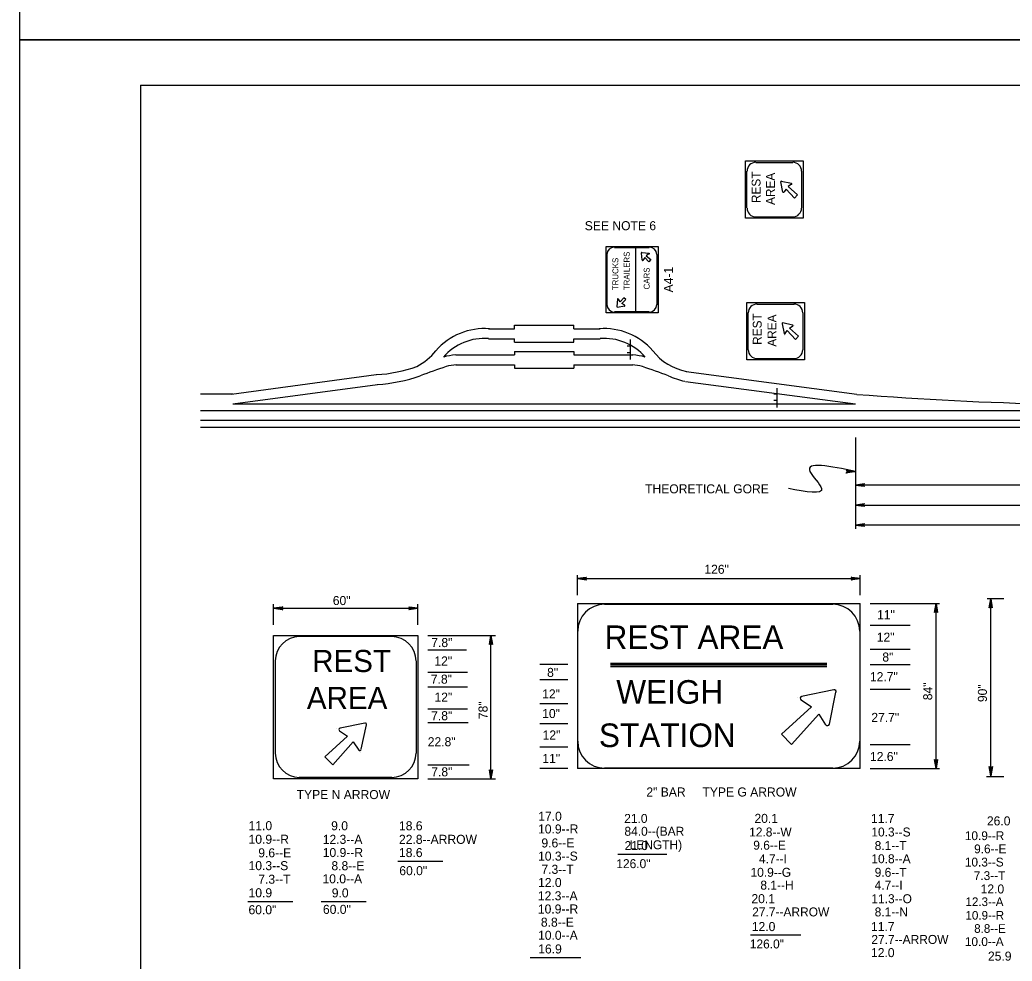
# Model space of a CAD drawing. Extents: x 649604 to 650509, y 298458 to 299646.
# Drawn here: x 649604.3 to 649933.2, y 298746.1 to 299058.3 of the extents above; entities that cross this region are included whole.
import ezdxf

# ---------------------------------------------------------------- set-up
doc = ezdxf.new("R2010")
doc.units = 0
for name, color, linetype in [('1', 7, 'Continuous'), ('2', 7, 'Continuous'), ('3', 7, 'Continuous'), ('PLT-BNDY', 7, 'Continuous')]:
    doc.layers.add(name, color=color, linetype=linetype)

# ---------------------------------------------------------------- blocks, each defined once
blk = doc.blocks.new('RARROW')
at = {"layer": '3'}
blk.add_lwpolyline([(-2.2695, 0.285), (-2.184875, 0.12075), (0, 0), (-2.2695, 0.285), (-2.38575, 0.384625), (0, 0), (-2.183125, -0.108), (-2.262875, -0.2705), (0, 0), (-2.38575, -0.379125), (-2.262875, -0.2705)], dxfattribs=at)

msp = doc.modelspace()

# ---------------------------------------------------------------- linework, layer by layer
at = {"layer": '1'}
for q in [(650430.31, 299036.63), (649644.31, 298472.63)]:
    msp.add_line((649644.31, 299036.63), q, dxfattribs=at)
at = {"layer": '2'}
for p, q in [((649848.31, 299011), (649860.56, 299011)), ((649856.56, 299004.75), (649856.56, 299004.75)), ((649857.19, 299001.13), (649856.56, 299004.5)), ((649856.69, 299004.75), (649860.06, 299004.13)), ((649860.06, 299003.75), (649858.94, 299003)), ((649858.31, 299002.13), (649857.56, 299001.13)), ((649861.06, 298999.13), (649858.31, 299002.13)), ((649858.31, 299002.13), (649858.31, 299002.13)), ((649858.94, 299003), (649858.94, 299003)), ((649858.94, 299003), (649862.06, 299000.25)), ((649862.06, 299000.25), (649861.06, 298999.13)), ((649863.94, 298992.5), (649844.81, 298992.5)), ((649860.56, 298992.88), (649848.31, 298992.88)), ((649801.44, 298982.75), (649812.94, 298982.75)), ((649808.44, 298961.5), (649808.44, 298982.75)), ((649810.56, 298978.63), (649810.31, 298980.88)), ((649810.56, 298981.13), (649812.81, 298980.88)), ((649810.56, 298981), (649810.56, 298981)), ((649812.81, 298980.63), (649811.94, 298980)), ((649812.81, 298980.63), (649812.81, 298980.63)), ((649812.94, 298980.63), (649812.94, 298980.63)), ((649812.94, 298980.63), (649812.94, 298980.63)), ((649810.69, 298978.63), (649810.69, 298978.63)), ((649810.69, 298978.38), (649810.69, 298978.38)), ((649810.69, 298978.38), (649810.69, 298978.38)), ((649811.44, 298979.5), (649810.81, 298978.5)), ((649812.81, 298978), (649811.44, 298979.5)), ((649811.44, 298979.5), (649811.44, 298979.5)), ((649811.69, 298979.75), (649811.69, 298979.75)), ((649811.94, 298980), (649811.94, 298980)), ((649811.94, 298980), (649813.44, 298978.75)), ((649813.44, 298978.75), (649812.81, 298978)), ((649812.81, 298978), (649812.81, 298978)), ((649813.44, 298978.75), (649813.44, 298978.75)), ((649802.44, 298965.63), (649802.19, 298963.25)), ((649802.56, 298965.88), (649802.56, 298965.88)), ((649803.31, 298964.75), (649802.69, 298965.63)), ((649804.56, 298966.13), (649803.31, 298964.75)), ((649803.81, 298964.25), (649805.19, 298965.5)), ((649803.81, 298964.25), (649803.81, 298964.25)), ((649804.81, 298963.63), (649803.81, 298964.25)), ((649805.19, 298965.5), (649804.56, 298966.13)), ((649800.94, 298961.13), (649799.31, 298961.13)), ((649801.44, 298961.5), (649812.94, 298961.5)), ((649802.19, 298963.13), (649802.19, 298963.13)), ((649802.31, 298963), (649804.81, 298963.38)), ((649804.81, 298963.5), (649804.81, 298963.5)), ((649804.81, 298963.5), (649804.81, 298963.5)), ((649808.81, 298961.13), (649807.81, 298961.13)), ((649848.69, 298964), (649860.94, 298964)), ((649856.81, 298957.75), (649856.81, 298957.75)), ((649860.44, 298957), (649857.19, 298957.75)), ((649759.69, 298955.75), (649768.31, 298955.75)), ((649768.31, 298957), (649787.94, 298957)), ((649768.31, 298955.75), (649768.31, 298957)), ((649787.94, 298955.75), (649787.94, 298957)), ((649787.94, 298955.75), (649796.69, 298955.75)), ((649856.94, 298957.5), (649857.69, 298954.25)), ((649857.94, 298954.25), (649858.69, 298955.25)), ((649858.69, 298955.25), (649858.69, 298955.25)), ((649858.69, 298955.25), (649861.44, 298952.25)), ((649859.44, 298956), (649860.56, 298956.75)), ((649862.44, 298953.38), (649859.44, 298956)), ((649859.44, 298956), (649859.44, 298956)), ((649860.94, 298957), (649860.94, 298957)), ((649759.69, 298952.5), (649768.31, 298952.5)), ((649768.31, 298951.38), (649768.31, 298952.5)), ((649768.31, 298951.38), (649787.94, 298951.38)), ((649787.94, 298951.38), (649787.94, 298952.5)), ((649787.94, 298952.5), (649796.69, 298952.5)), ((649806.69, 298945.63), (649806.69, 298952.25)), ((649857.81, 298953.75), (649857.81, 298953.75)), ((649861.44, 298952.25), (649862.44, 298953.38)), ((649768.31, 298948.25), (649787.94, 298948.25)), ((649768.31, 298948.25), (649768.31, 298947.13)), ((649787.94, 298948.25), (649787.94, 298947.13)), ((649806.69, 298950), (649805.56, 298950)), ((649806.69, 298947.88), (649805.56, 298947.88)), ((649748.81, 298947.13), (649768.31, 298947.13)), ((649787.94, 298947.13), (649807.44, 298947.13)), ((649864.44, 298945.5), (649845.31, 298945.5)), ((649860.94, 298945.88), (649848.69, 298945.88)), ((649748.81, 298943.88), (649768.31, 298943.88)), ((649768.31, 298943.88), (649768.31, 298942.75)), ((649768.31, 298942.75), (649787.94, 298942.75)), ((649787.94, 298943.88), (649787.94, 298942.75)), ((649787.94, 298943.88), (649807.44, 298943.88)), ((649825.19, 298941.63), (649881.69, 298934.13)), ((649674.44, 298934.13), (649722.44, 298940.63)), ((649824.94, 298938.38), (649824.94, 298938.38)), ((649824.94, 298938.38), (649881.31, 298930.88)), ((649674.94, 298930.88), (649722.81, 298937.38)), ((649722.81, 298937.38), (649722.81, 298937.38)), ((649722.81, 298937.38), (649722.81, 298937.38)), ((649855.31, 298929.75), (649855.31, 298936.13)), ((649674.94, 298934.13), (649664.19, 298934.13)), ((649855.31, 298934.13), (649854.19, 298934.13)), ((649855.31, 298932), (649854.19, 298932)), ((649664.19, 298928.75), (650390.69, 298928.75)), ((649674.94, 298930.88), (649881.31, 298930.88)), ((649674.94, 298930.88), (649674.94, 298930.88)), ((649674.94, 298930.88), (649674.94, 298930.88)), ((649664.19, 298925.5), (650390.69, 298925.5)), ((649664.19, 298923.25), (650390.69, 298923.25)), ((649881.31, 298919.75), (649881.31, 298889.5)), ((650085.69, 298904), (649881.31, 298904)), ((649881.31, 298897.38), (650176.94, 298897.38)), ((650311.69, 298890.75), (649881.31, 298890.75)), ((649789.13, 298867.47), (649789.13, 298874.13)), ((649789.13, 298873), (649882.88, 298873)), ((649882.88, 298867.47), (649882.88, 298874.13)), ((649930.47, 298866.25), (649924.9, 298866.25)), ((649926.15, 298807.63), (649926.15, 298866.25)), ((649688.44, 298857.65), (649688.44, 298864.5)), ((649688.44, 298863.13), (649736.19, 298863.13)), ((649736.19, 298857.65), (649736.19, 298864.5)), ((649789.13, 298864.75), (649882.88, 298864.75)), ((649789.13, 298864.75), (649789.13, 298810)), ((649798.15, 298864.49), (649873.75, 298864.49)), ((649882.88, 298810), (649882.88, 298864.75)), ((649886.17, 298864.75), (649909.12, 298864.75)), ((649908, 298810), (649908, 298864.75)), ((649886.17, 298857.5), (649899.45, 298857.5)), ((649688.44, 298806.63), (649688.44, 298854.13)), ((649739.56, 298854.13), (649761.94, 298854.13)), ((649760.44, 298806.63), (649760.44, 298854.13)), ((649789.21, 298819.06), (649789.21, 298855.55)), ((649882.7, 298855.55), (649882.7, 298819.06)), ((649739.56, 298849.38), (649752.33, 298849.38)), ((649886.17, 298849.63), (649899.45, 298849.63)), ((649688.94, 298845.63), (649688.94, 298815.13)), ((649735.81, 298815.13), (649735.81, 298845.63)), ((649785.9, 298844.5), (649776.63, 298844.5)), ((649800.13, 298845), (649871.76, 298845)), ((649800.13, 298844.88), (649871.76, 298844.88)), ((649800.13, 298844.5), (649871.76, 298844.5)), ((649800.13, 298844), (649871.76, 298844)), ((649800.13, 298843.88), (649871.76, 298843.88)), ((649886.17, 298844.5), (649899.45, 298844.5)), ((649739.56, 298842), (649752.68, 298842)), ((649785.9, 298839.38), (649776.63, 298839.38)), ((649739.56, 298837.13), (649752.68, 298837.13)), ((649874.13, 298836.13), (649863.38, 298833.88)), ((649874.13, 298836.13), (649863.38, 298833.88)), ((649875.01, 298836.38), (649875.01, 298836.38)), ((649886.17, 298836.38), (649899.45, 298836.38)), ((649862.01, 298833.63), (649862.01, 298833.63)), ((649863.26, 298832.75), (649866.76, 298830.5)), ((649863.26, 298832.75), (649866.76, 298830.5)), ((649872.63, 298824.75), (649874.76, 298835.38)), ((649872.63, 298824.75), (649874.76, 298835.38)), ((649739.56, 298829.75), (649752.68, 298829.75)), ((649785.9, 298831.5), (649776.63, 298831.5)), ((649866.76, 298830.5), (649856.76, 298821.38)), ((649866.76, 298830.5), (649856.76, 298821.38)), ((649866.76, 298830.5), (649866.76, 298830.5)), ((649867.88, 298829.25), (649867.88, 298829.25)), ((649860.13, 298818), (649869.13, 298828)), ((649860.13, 298818), (649869.13, 298828)), ((649869.13, 298828), (649871.38, 298824.5)), ((649869.13, 298828), (649869.13, 298828)), ((649869.13, 298828), (649871.38, 298824.5)), ((649709.31, 298823.13), (649709.31, 298823.13)), ((649718.69, 298825), (649710.44, 298823.38)), ((649717.44, 298816.38), (649719.19, 298824.5)), ((649719.31, 298825.25), (649719.31, 298825.25)), ((649739.56, 298825.25), (649752.91, 298825.25)), ((649785.9, 298824.88), (649776.63, 298824.88)), ((649872.38, 298823.25), (649872.38, 298823.25)), ((649712.94, 298820.75), (649705.44, 298813.88)), ((649710.31, 298822.5), (649712.94, 298820.75)), ((649712.94, 298820.75), (649712.94, 298820.75)), ((649856.76, 298821.38), (649860.13, 298818)), ((649856.76, 298821.38), (649856.76, 298821.38)), ((649856.76, 298821.38), (649860.13, 298818)), ((649708.06, 298811.25), (649714.81, 298818.88)), ((649714.81, 298818.88), (649714.81, 298818.88)), ((649714.81, 298818.88), (649716.69, 298816.13)), ((649785.9, 298817.13), (649776.63, 298817.13)), ((649860.13, 298818), (649860.13, 298818)), ((649886.17, 298818), (649899.45, 298818)), ((649705.44, 298813.88), (649708.06, 298811.25)), ((649717.19, 298815.25), (649717.19, 298815.25)), ((649739.56, 298811.25), (649753.26, 298811.25)), ((649785.9, 298810), (649776.63, 298810)), ((649882.88, 298810), (649789.13, 298810)), ((649873.75, 298810.12), (649798.15, 298810.12)), ((649886.17, 298810), (649909.12, 298810)), ((649739.56, 298806.63), (649761.94, 298806.63)), ((649930.47, 298807.27), (649924.77, 298807.27)), ((649802.47, 298781.61), (649818.72, 298781.61)), ((649729.65, 298779.34), (649744.51, 298779.34)), ((649679.92, 298765.97), (649694.77, 298765.97)), ((649704.19, 298765.97), (649719.1, 298765.97)), ((649846.53, 298754.86), (649863.15, 298754.86)), ((649773.49, 298747.38), (649790.28, 298747.38))]:
    msp.add_line(p, q, dxfattribs=at)
for points in [[(649844.81, 298992.5), (649844.81, 299011.5), (649846.81, 299011.5), (649849.81, 299011.5), (649851.69, 299011.5), (649854.56, 299011.5), (649856.56, 299011.5), (649862.19, 299011.5), (649863.94, 299011.5), (649863.94, 299011.5), (649863.94, 298992.5), (649863.94, 298992.5)], [(649845.31, 298995.88), (649845.31, 299008.13)], [(649863.44, 299008.13), (649863.44, 298995.88)], [(649798.69, 298961.13), (649798.69, 298983.13), (649800.31, 298983.13), (649802.19, 298983.13), (649803.69, 298983.13), (649805.69, 298983.13), (649807.06, 298983.13), (649808.56, 298983.13), (649811.81, 298983.13), (649815.94, 298983.13), (649815.94, 298961.13), (649811.19, 298961.13), (649809.31, 298961.13), (649807.06, 298961.13), (649804.69, 298961.13), (649801.44, 298961.13), (649798.69, 298961.13)], [(649798.94, 298963.75), (649798.94, 298980.5)], [(649815.44, 298980.5), (649815.44, 298963.75)], [(649845.31, 298945.5), (649845.31, 298964.5), (649847.31, 298964.5), (649850.19, 298964.5), (649852.06, 298964.5), (649855.06, 298964.5), (649856.81, 298964.5), (649862.56, 298964.5), (649864.44, 298964.5), (649864.44, 298964.5), (649864.44, 298945.5), (649864.44, 298945.5)], [(649845.69, 298948.88), (649845.69, 298961.13)], [(649863.81, 298961.13), (649863.81, 298948.88)], [(649688.44, 298854.13), (649736.19, 298854.13), (649736.19, 298849.38), (649736.19, 298842), (649736.19, 298837.13), (649736.19, 298829.75), (649736.19, 298825.25), (649736.19, 298811.25), (649736.19, 298806.63), (649736.19, 298806.63), (649688.44, 298806.63), (649688.44, 298806.63)], [(649727.56, 298853.75), (649696.94, 298853.75)], [(649696.94, 298807.13), (649727.56, 298807.13)]]:
    msp.add_lwpolyline(points, dxfattribs=at)
for centre, radius, start, end in [((649848.27, 299008.08), 2.93, 90, 180), ((649860.49, 299008.08), 2.93, 0, 90), ((649856.7, 299004.54), 0.183, 78.0958, 191.9043), ((649856.7, 299004.54), 0.183, 78.0958, 191.9043), ((649859.98, 299003.85), 0.183, 302.692, 78.0958), ((649859.98, 299003.85), 0.183, 302.692, 78.0958), ((649857.39, 299001.26), 0.183, 191.9043, 327.308), ((649857.39, 299001.26), 0.183, 191.9042, 327.308), ((649848.27, 298995.86), 2.93, 180, 270), ((649860.49, 298995.86), 2.93, 270, 0), ((649801.36, 298980.44), 2.44, 90, 180), ((649810.44, 298981), 0.153, 84.0498, 185.9502), ((649812.84, 298980.75), 0.153, 301.5539, 84.0498), ((649812.99, 298980.44), 2.44, 0, 90), ((649810.69, 298978.6), 0.153, 185.9502, 328.4461), ((649802.55, 298965.61), 0.153, 31.5539, 174.0498), ((649801.36, 298963.82), 2.44, 180, 270), ((649802.3, 298963.22), 0.153, 174.0498, 275.9502), ((649804.69, 298963.47), 0.153, 275.9502, 58.4461), ((649812.99, 298963.82), 2.44, 270, 0), ((649848.69, 298961.09), 2.93, 90, 180), ((649860.91, 298961.09), 2.93, 0, 90), ((649857.12, 298957.56), 0.183, 78.0958, 191.9043), ((649857.12, 298957.56), 0.183, 78.0958, 191.9043), ((649758.25, 298934.67), 21.21, 85.4134, 139.1043), ((649798.05, 298934.67), 21.21, 40.8957, 94.5866), ((649857.81, 298954.27), 0.183, 191.9043, 327.308), ((649857.81, 298954.27), 0.183, 191.9043, 327.308), ((649860.4, 298956.87), 0.183, 302.692, 78.0958), ((649860.4, 298956.87), 0.183, 302.692, 78.0958), ((649758.25, 298934.67), 17.95, 85.4134, 139.1043), ((649798.05, 298934.67), 17.95, 40.8957, 94.5866), ((649727.53, 298959.9), 18.56, 296.8793, 322.3109), ((649828.77, 298959.9), 18.56, 217.6891, 259.2048), ((649848.69, 298948.87), 2.93, 180, 270), ((649860.91, 298948.87), 2.93, 270, 0), ((649749.74, 298929.33), 17.82, 92.9526, 106.4866), ((649806.56, 298929.33), 17.82, 73.5134, 87.0474), ((649719.77, 298988.56), 48.03, 273.3346, 289.6636), ((651988.02, 292598.03), 6729.85, 109.463364, 109.540836), ((649749.74, 298929.33), 14.56, 92.9526, 106.4866), ((649806.56, 298929.33), 14.56, 73.5134, 87.0474), ((647568.28, 292598.03), 6729.85, 70.459164, 70.536636), ((649719.77, 298988.56), 51.29, 273.3346, 289.6636), ((649828.77, 298959.9), 21.82, 244.1957, 259.2048), ((649975.83, 300169.06), 1238.57, 265.6447, 268.64351), ((649798.15, 298855.55), 8.94, 90, 180), ((649873.75, 298855.55), 8.94, 0, 90), ((649697.03, 298845.68), 8.08, 90, 180), ((649727.58, 298845.68), 8.08, 0, 90), ((649874.21, 298835.48), 0.659, 348.2602, 101.7398), ((649874.21, 298835.48), 0.659, 348.2602, 101.7398), ((649863.63, 298833.28), 0.659, 101.7398, 236.6838), ((649863.63, 298833.28), 0.659, 101.7398, 236.6838), ((649710.53, 298822.89), 0.458, 101.9043, 237.308), ((649710.53, 298822.89), 0.458, 101.9043, 237.308), ((649718.74, 298824.62), 0.458, 348.0958, 101.9043), ((649718.74, 298824.62), 0.458, 348.0958, 101.9043), ((649872.01, 298824.9), 0.659, 213.3162, 348.2602), ((649872.01, 298824.9), 0.659, 213.3162, 348.2602), ((649717.01, 298816.41), 0.458, 212.692, 348.0958), ((649717.01, 298816.41), 0.458, 212.692, 348.0957), ((649798.15, 298819.06), 8.94, 180, 270), ((649873.75, 298819.06), 8.94, 270, 0), ((649697.03, 298815.13), 8.08, 180, 270), ((649727.58, 298815.13), 8.08, 270, 0)]:
    msp.add_arc(centre, radius, start, end, dxfattribs=at)
msp.add_spline([(649881.31, 298908.5), (649866.19, 298908.5), (649870.06, 298902.88), (649859.06, 298902.88)], degree=3, dxfattribs=at)
at = {"layer": 'PLT-BNDY'}
for points in [[(649604.31, 299645.63), (650445.31, 299645.63), (650445.31, 299051.63), (649604.31, 299051.63)], [(649604.31, 299051.63), (650445.31, 299051.63), (650445.31, 298457.63), (649604.31, 298457.63)]]:
    msp.add_lwpolyline(points, close=True, dxfattribs=at)

# ---------------------------------------------------------------- block references
at = {"layer": '2', "xscale": 1.2574347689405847, "yscale": 1.3092961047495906}
for p in [(649881.17, 298908.48), (649882.88, 298873), (649736.19, 298863.13)]:
    msp.add_blockref('RARROW', p, dxfattribs=at)
for p, rotation in [((649881.31, 298904), 180), ((649881.31, 298897.38), 180), ((649881.31, 298890.75), 180), ((649789.13, 298873), 180), ((649926.15, 298866.25), 89.99999999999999), ((649688.44, 298863.13), 180), ((649908, 298864.75), 89.99999999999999), ((649760.44, 298854.13), 89.99999999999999), ((649908, 298810), -90.00000000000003), ((649760.44, 298806.63), -90.00000000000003), ((649926.15, 298807.63), -90.00000000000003)]:
    msp.add_blockref('RARROW', p, dxfattribs=dict(at, rotation=rotation))

# ---------------------------------------------------------------- texts
at = {"layer": '2'}
for s, height, p in [('REST', 2.932, (649849.81, 298997.5)), ('AREA', 2.932, (649854.56, 298996.88)), ('TRAILERS', 1.955, (649806.44, 298968.63)), ('TRUCKS', 1.955, (649802.69, 298968.63)), ('CARS', 1.955, (649813.06, 298968.88)), ('A4-1', 3, (649820.81, 298967.88)), ('REST', 2.932, (649850.19, 298950.5)), ('AREA', 2.932, (649855.06, 298949.88)), ('84"', 3, (649906.74, 298832.66)), ('90"', 3, (649924.86, 298832.03)), ('78"', 3, (649759.35, 298826.39))]:
    msp.add_text(s, height=height, rotation=90, dxfattribs=at).set_placement(p)
for s, height, p in [('SEE NOTE 6', 3, (649791.56, 298988.5)), ('THEORETICAL GORE', 3, (649811.56, 298901.25)), ('126"', 3, (649831.2, 298874.58)), ('60"', 3, (649708.04, 298864.21)), ('11"', 3, (649888.44, 298859.52)), ('REST AREA', 7.82, (649798.13, 298849.63)), ('7.8"', 3, (649740.68, 298850.28)), ('12"', 3, (649888.35, 298852.07)), ('REST', 7.33, (649701.19, 298842)), ('12"', 3, (649741.71, 298844.17)), ('8"', 3, (649890.19, 298845.47)), ('8"', 3, (649779.08, 298840.38)), ('7.8"', 3, (649740.54, 298838.15)), ('WEIGH', 7.82, (649802.01, 298831.5)), ('12.7"', 3, (649886.08, 298838.97)), ('AREA', 7.33, (649699.44, 298829.75)), ('12"', 3, (649777.45, 298833.25)), ('12"', 3, (649741.75, 298832.18)), ('10"', 3, (649777.45, 298826.75)), ('7.8"', 3, (649740.65, 298826.02)), ('27.7"', 3, (649886.54, 298825.46)), ('12"', 3, (649777.59, 298819.63)), ('STATION', 7.82, (649796.26, 298817.13)), ('22.8"', 3, (649739.51, 298817.39)), ('11"', 3, (649777.5, 298811.86)), ('12.6"', 3, (649886.1, 298812.5)), ('7.8"', 3, (649740.68, 298807.42)), ('2" BAR     TYPE G ARROW', 3, (649811.97, 298800.73)), ('TYPE N ARROW', 3, (649696.06, 298799.88)), ('17.0   ', 3, (649776.14, 298792.69)), ('21.0             ', 2.9663, (649804.64, 298791.98)), ('20.1      ', 3, (649847.8, 298791.98)), ('11.7       ', 3, (649886.43, 298791.98)), ('26.0', 3, (649924.85, 298791.15)), ('11.0   ', 3, (649680.12, 298789.56)), ('9.0   ', 3, (649707.5, 298789.53)), ('18.6       ', 3, (649729.98, 298789.53)), ('10.9--R', 3, (649776.08, 298788.47)), ('84.0--(BAR', 2.966, (649804.71, 298787.72)), (' 12.8--W    ', 2.9663, (649844.94, 298787.48)), ('10.3--S    ', 2.9663, (649886.55, 298787.48)), ('10.9--R', 3, (649680.12, 298785.06)), ('12.3--A', 3, (649704.71, 298785.03)), ('22.8--ARROW', 3, (649729.98, 298785.03)), (' 9.6--E', 3, (649776.08, 298783.84)), ('    10.9--R', 2.931, (649913.19, 298786.27)), ('9.6--E', 3, (649683.34, 298780.56)), ('10.9--R', 3, (649704.71, 298780.66)), ('18.6       ', 3, (649729.98, 298780.65)), ('21.0', 2.966, (649804.76, 298782.98)), ('         LENGTH)', 2.9663, (649796.5, 298783.25)), ('  9.6--E     ', 2.9663, (649845.2, 298783.1)), (' 8.1--T    ', 2.9663, (649886.55, 298782.98)), ('    9.6--E', 2.931, (649916.27, 298781.9)), ('10.3--S', 3, (649776.08, 298779.47)), ('126.0"             ', 2.9663, (649802.01, 298776.98)), (' 4.7--I    ', 2.9663, (649848.21, 298778.61)), ('10.8--A    ', 2.9663, (649886.55, 298778.61)), ('    10.3--S', 2.931, (649913.19, 298777.52)), ('10.3--S', 3, (649680.12, 298776.31)), ('8.8--E', 3, (649707.59, 298776.28)), ('60.0"        ', 3, (649730.09, 298774.65)), (' 7.3--T', 3, (649776.08, 298775.09)), (' 10.9--G    ', 2.9663, (649845.39, 298774.11)), (' 9.6--T    ', 2.9663, (649886.55, 298774.11)), ('7.3--T', 3, (649683.34, 298771.81)), ('10.0--A', 3, (649704.62, 298771.94)), ('12.0   ', 3, (649776.08, 298770.72)), ('    7.3--T', 2.931, (649916.15, 298773.03)), ('10.9   ', 3, (649680.12, 298767.31)), ('9.0   ', 3, (649707.71, 298767.28)), (' 8.1--H    ', 2.9663, (649848.66, 298769.86)), (' 4.7--I    ', 2.9663, (649886.55, 298769.86)), (' 12.0', 3, (649921.65, 298768.58)), ('12.3--A', 3, (649776.02, 298766.31)), (' 20.1       ', 3, (649845.69, 298765.36)), ('11.3--O    ', 2.9663, (649886.55, 298765.36)), ('    12.3--A', 2.8748, (649913.47, 298764.4)), ('60.0"    ', 3, (649680.1, 298761.69)), ('60.0"    ', 3, (649704.78, 298761.81)), ('10.9--R', 3, (649776.02, 298761.94)), (' 27.7--ARROW', 2.9663, (649845.95, 298760.98)), (' 8.1--N    ', 2.9663, (649886.55, 298760.98)), (' 8.8--E', 3, (649775.9, 298757.56)), ('    10.9--R', 2.8748, (649913.47, 298759.9)), (' 12.0       ', 3, (649845.81, 298756.11)), ('11.7       ', 3, (649886.43, 298756.11)), ('    8.8--E', 2.875, (649916.36, 298755.52)), ('10.0--A', 3, (649776.08, 298753.22)), ('27.7--ARROW', 2.9663, (649886.55, 298751.86)), ('    10.0--A', 2.931, (649913.19, 298751.15)), ('16.9   ', 3, (649776.14, 298748.69)), ('126.0"       ', 2.9663, (649846.25, 298750.36)), ('12.0', 3, (649886.44, 298747.48)), ('25.9', 3, (649925.2, 298746.31))]:
    msp.add_text(s, height=height, dxfattribs=at).set_placement(p)

doc.saveas('drawing.dxf')
